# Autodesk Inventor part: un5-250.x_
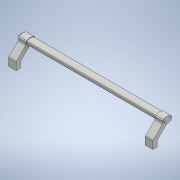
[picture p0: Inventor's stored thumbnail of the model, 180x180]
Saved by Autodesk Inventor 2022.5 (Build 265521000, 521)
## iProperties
Part Number: un5-250.x_
Material: 一般
Document SubType Name: Modeling
Designer: ImaoCorp
Density: 1 g/cm^3
Appearance: 既定
Sending System: SOLIDWORKS 2017-2017317
MC: AMD64
MC_MODEL: Intel64 Family 6 Model 60 Stepping 3, GenuineIntel
OS: Windows_NT
FRU: Parasolid Version 29.0, build 201,  4-17-2017
FORMAT: text
GUISE: transmit
KEY: un5-250
FILE: un5-250.x_t
DATE: Thu Sep 19 11:10:24 2019
Author: ImaoCorp
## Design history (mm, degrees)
feature "Base1"
node "ソリッド1"
